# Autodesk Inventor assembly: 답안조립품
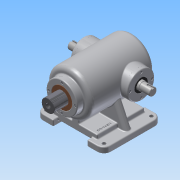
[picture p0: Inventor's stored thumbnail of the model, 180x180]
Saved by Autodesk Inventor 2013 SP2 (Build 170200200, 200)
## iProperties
Created: 2014-12
Part Number: 답안조립품
Document SubType Name: Assembly
Designer: Administrator
Mass: 8641.3 g
Surface Area: 4328.77 cm^2
Volume: 2314.18 cm^3
Density: 3.73407 g/cm^3
Author: Administrator
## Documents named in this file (13)
- C:\Users\Administrator\Desktop\341228V1001\답안조립품.iam
- C:\Users\Administrator\Desktop\341228V1001\본체.ipt
- C:\Users\Administrator\Desktop\341228V1001\슬라이드.ipt
- C:\Users\Administrator\Desktop\341228V1001\베어링 6205.ipt
- 베어링 6205.ipt
- C:\Users\Administrator\Desktop\341228V1001\축 커버.ipt
- C:\Users\Administrator\Desktop\341228V1001\오일실.ipt
- 오일실.ipt
- C:\Users\Administrator\Desktop\341228V1001\슬라이드 커버.ipt
- C:\Users\Administrator\Desktop\341228V1001\부시.ipt
- C:\Users\Administrator\Desktop\341228V1001\M4x0.7.ipt
- C:\Users\Administrator\Desktop\341228V1001\편심축.ipt
- C:\Users\Administrator\Desktop\341228V1001\스프링-[가변].ipt
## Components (12 placed, 1 different names)
1. M4x0.7:1 — 각도:1
2. M4x0.7:2
3. M4x0.7:3
4. M4x0.7:4
5. M4x0.7:5 — 각도:2
6. M4x0.7:6
7. M4x0.7:7
8. M4x0.7:8
9. M4x0.7:9 — 각도:3
10. M4x0.7:10
11. M4x0.7:11
12. M4x0.7:12
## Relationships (3: Angle 3)
- 각도:1 [Angle]: M4x0.7:1
- 각도:2 [Angle]: M4x0.7:5
- 각도:3 [Angle]: M4x0.7:9
